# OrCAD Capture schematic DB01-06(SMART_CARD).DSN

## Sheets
1 01. Power Supply: size Custom; title: System Power; rev: 1.0; company: MEGAWIN; note: DB01-06
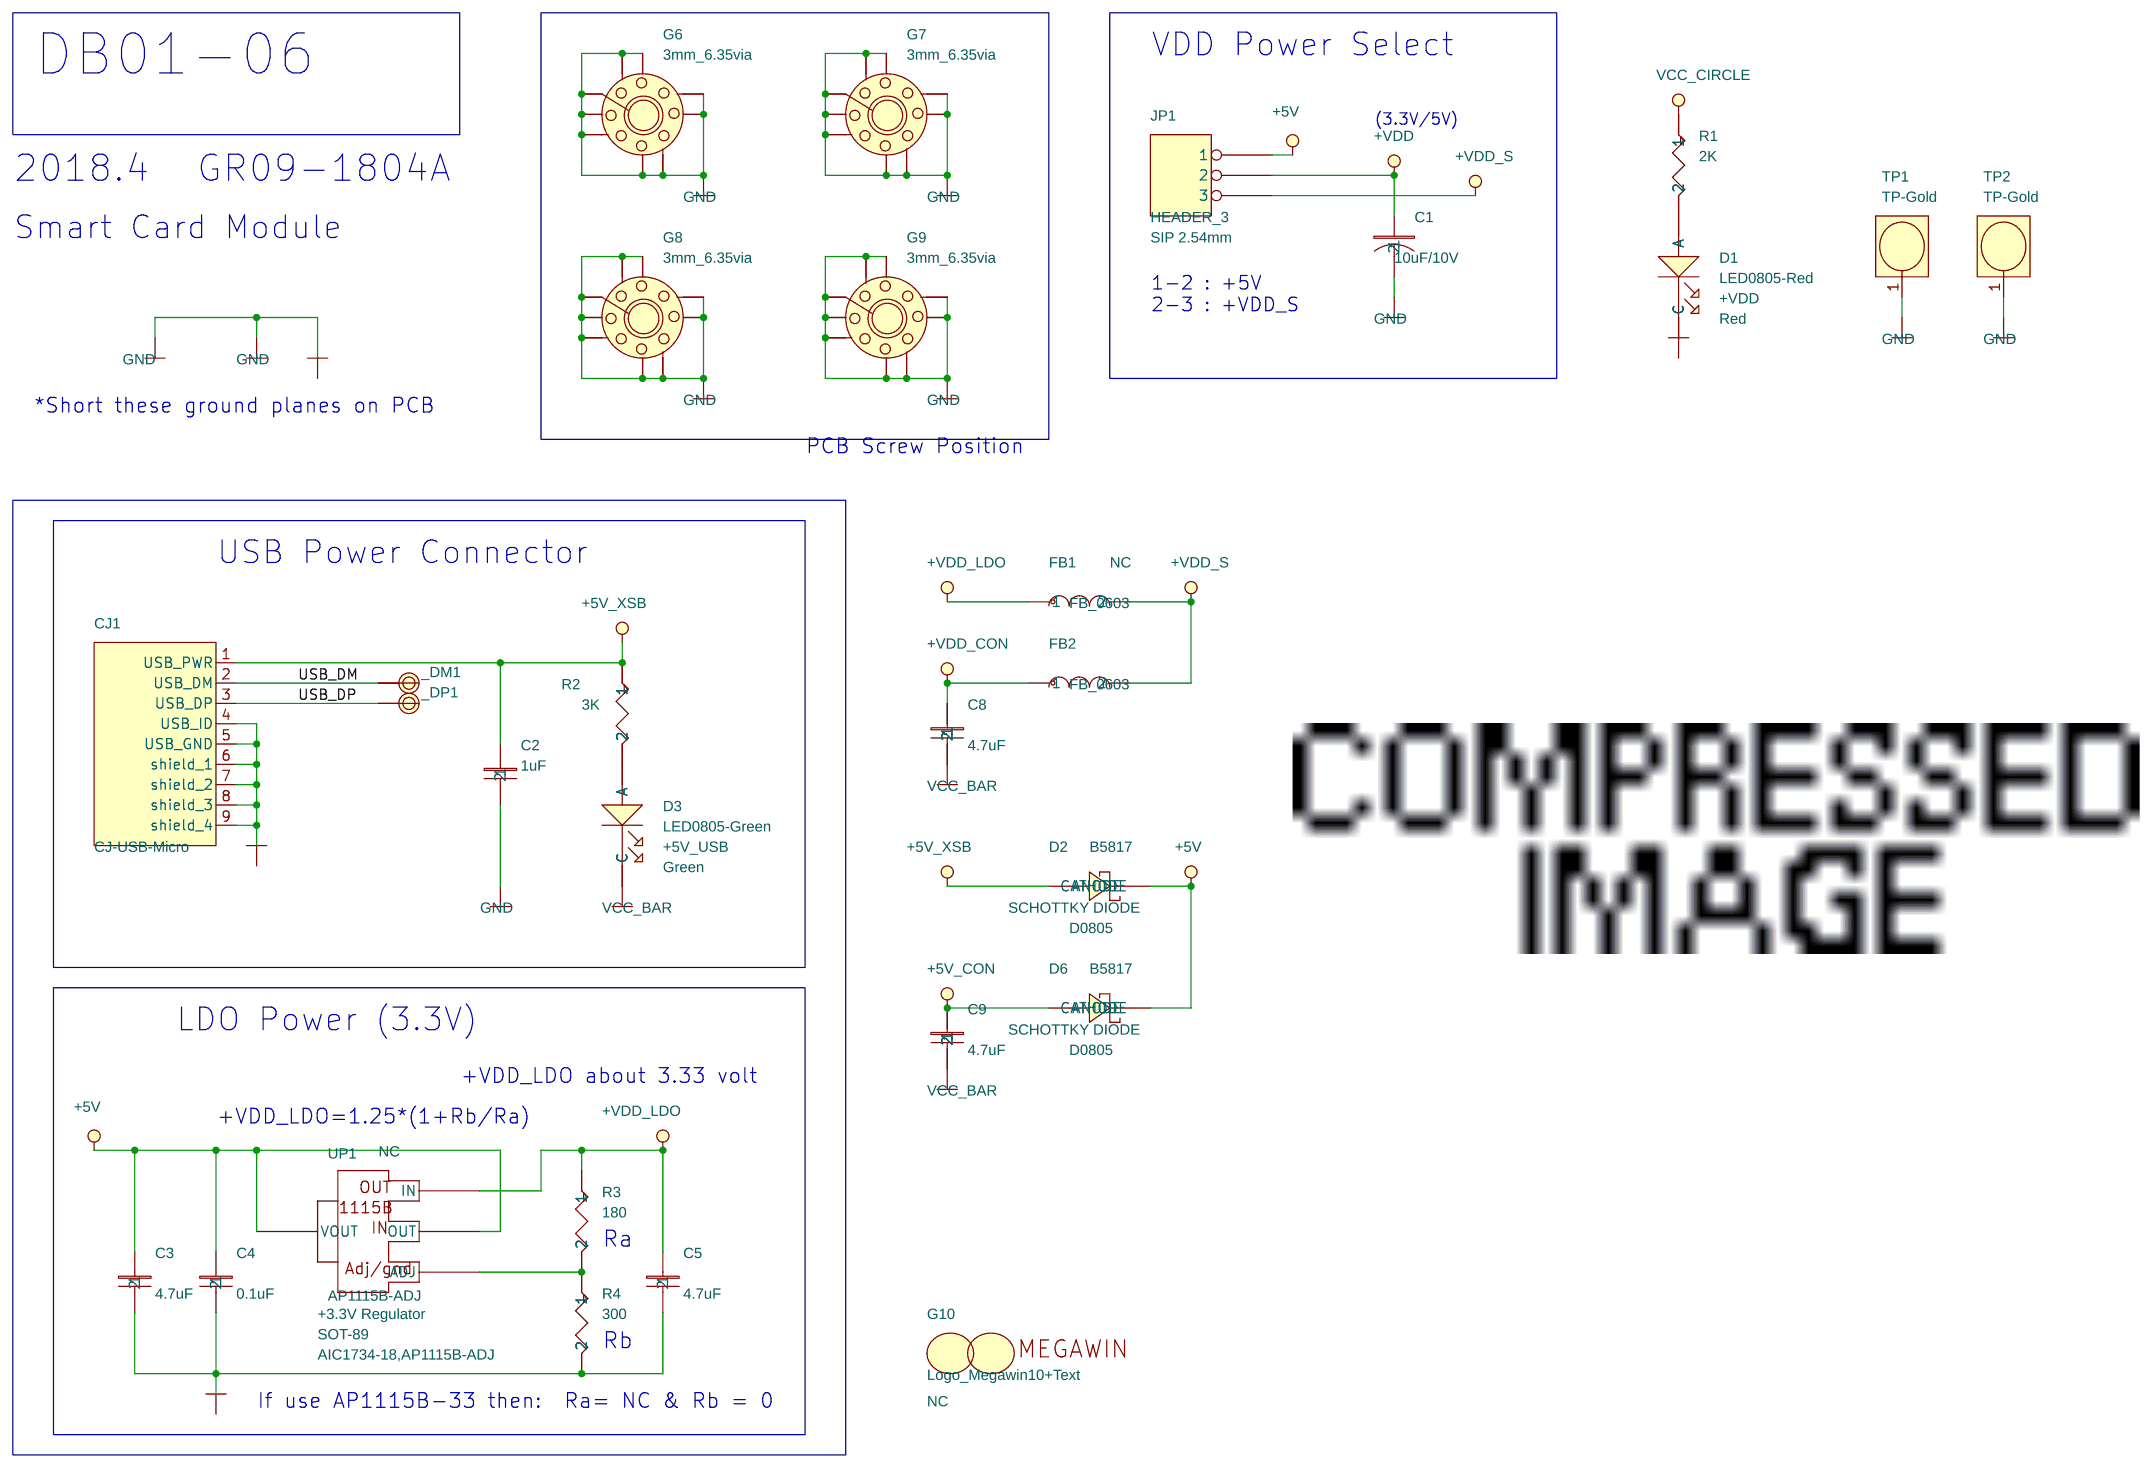
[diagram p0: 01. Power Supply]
2 02. Smart Card IF: size B; title: Smart Card Interface
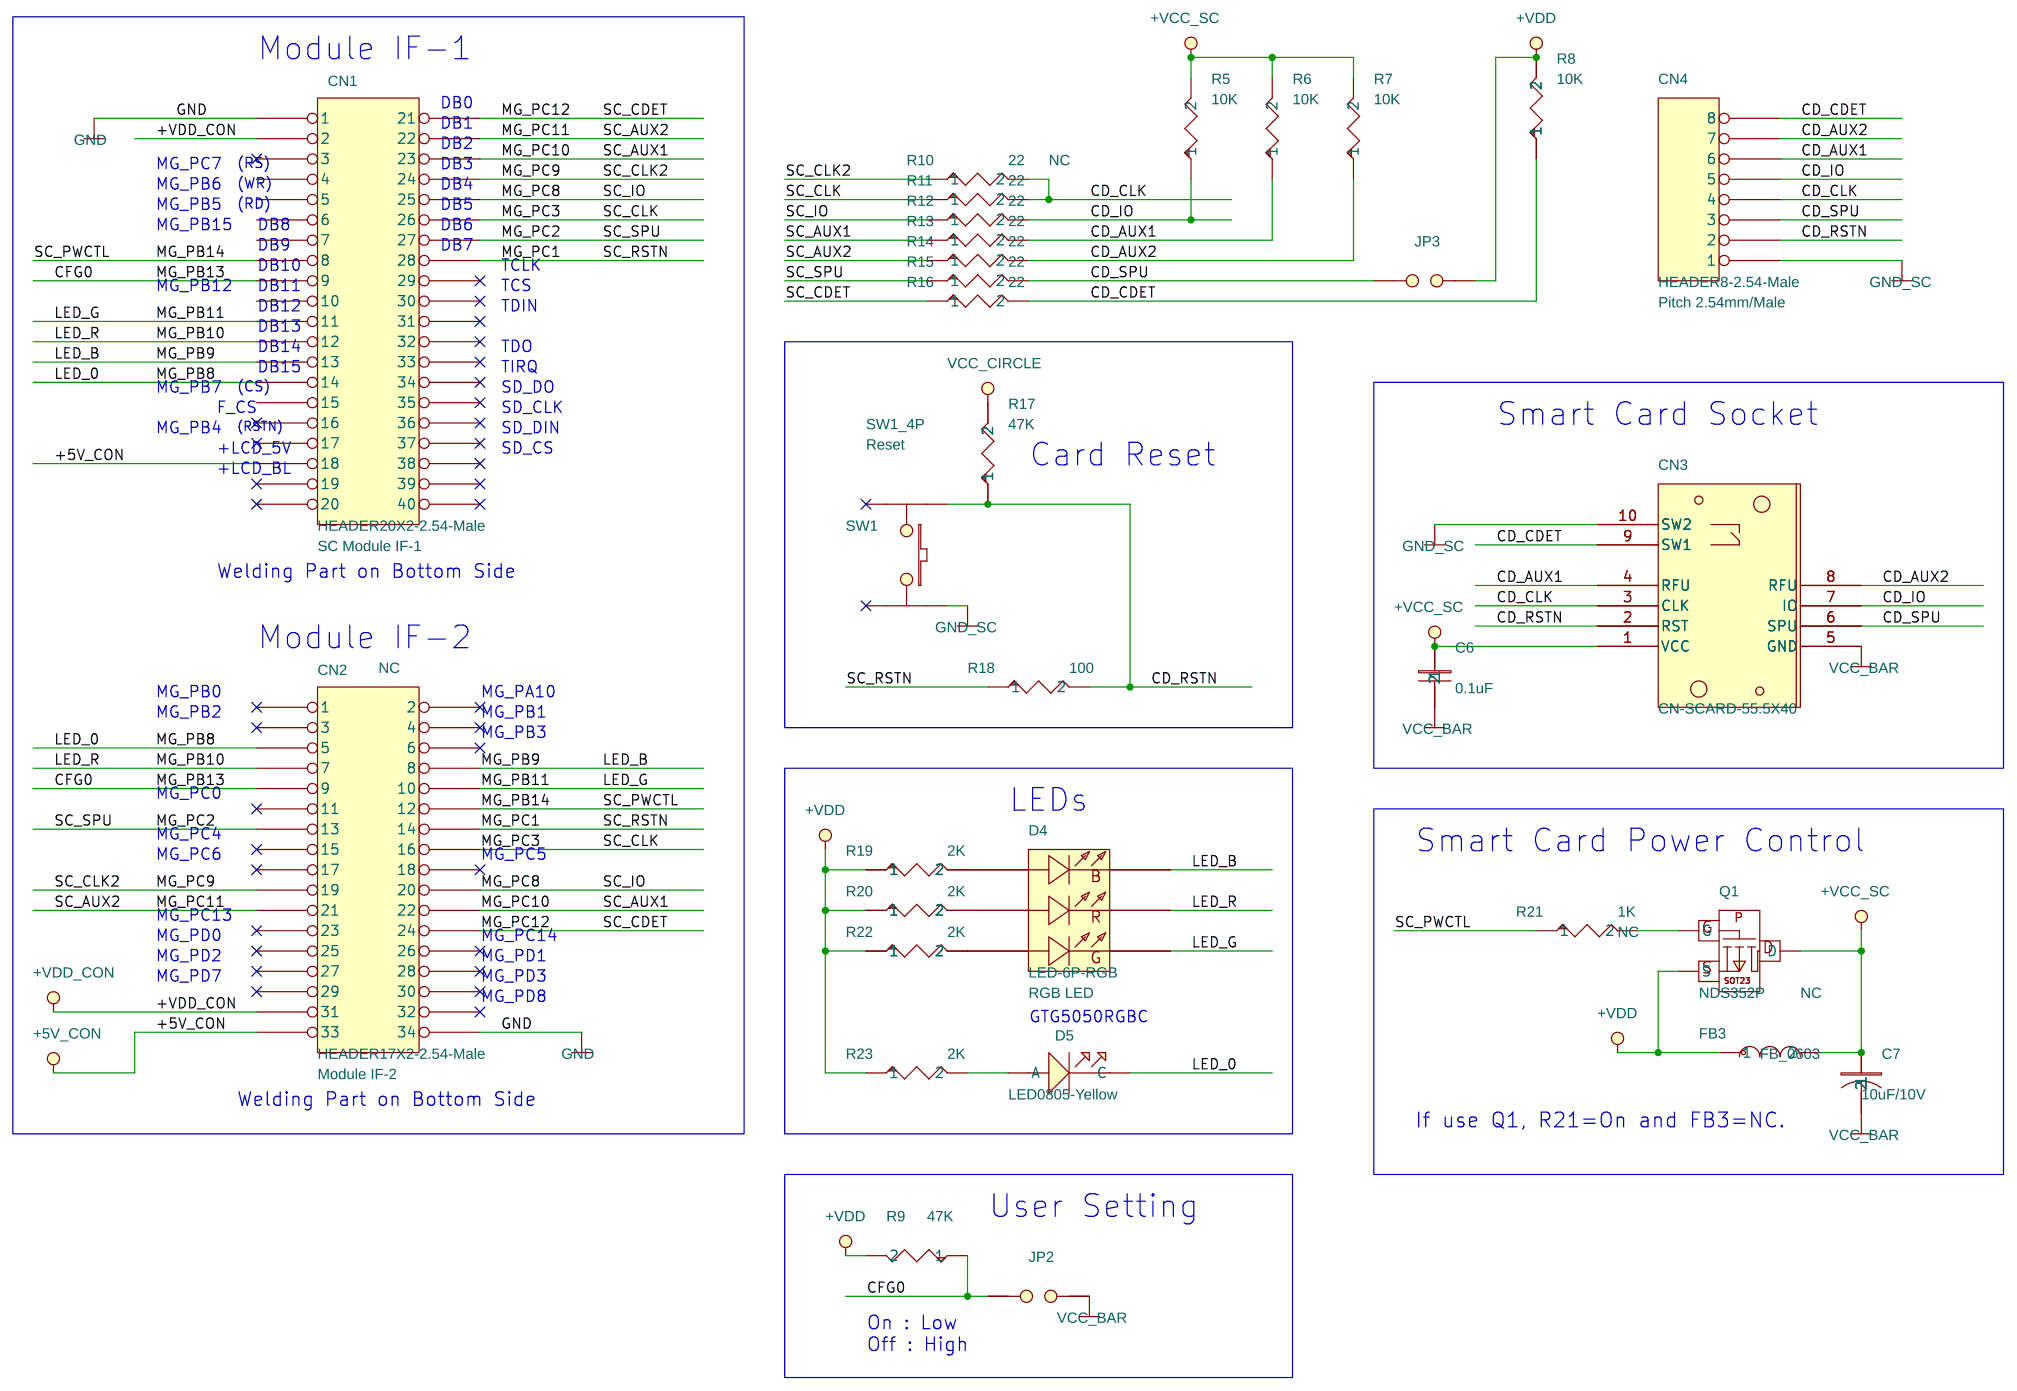
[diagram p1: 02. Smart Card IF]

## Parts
sheet 01. Power Supply
_DM1  TPH30  [TPH45]
_DP1  TPH30  [TPH45]
C1  10uF/10V  [C-0805]
C2  1uF  [C-0603]
C3  4.7uF  [C-0603]
C4  0.1uF  [C-0603]
C5  4.7uF  [C-0603]
C8  4.7uF  [C-0603]
C9  4.7uF  [C-0603]
CJ1  CJ-USB-Micro  [USB5-MICRO-290X220P065]
D1  LED0805-Red  [LED-0805]
D2  B5817  [D-0805]
D3  LED0805-Green  [LED-0805]
D6  B5817  [D-0805]
FB1  FB_0603  [L-0603]
FB2  FB_0603  [L-0603]
G6  3mm_6.35via  [SCREW9-H3-R6.35]
G7  3mm_6.35via  [SCREW9-H3-R6.35]
G8  3mm_6.35via  [SCREW9-H3-R6.35]
G9  3mm_6.35via  [SCREW9-H3-R6.35]
G10  Logo_Megawin10+Text  [MEGAWIN10_1]
JP1  HEADER_3  [SIP3-P2.54]
R1  2K  [R-0603]
R2  3K  [R-0603]
R3  180  [R-0603]
R4  300  [R-0603]
TP1  TP-Gold  [SIP1-39]
TP2  TP-Gold  [SIP1-39]
UP1  AP1115B-ADJ  [SOT-89-1]
sheet 02. Smart Card IF
C6  0.1uF  [C-0603]
C7  10uF/10V  [C-0805]
CN1  HEADER20X2-2.54-Male  [HD20X2A-P2.54]
CN2  HEADER17X2-2.54-Male  [HD17X2-P2.54]
CN3  CN-SCARD-55.5X40  [CARD-SMART-55.5X40]
CN4  HEADER8-2.54-Male  [SIP8-P2.54]
D4  LED-6P-RGB  [LED-6P-RGB-50X50]
D5  LED0805-Yellow  [LED-0805]
FB3  FB_0603  [L-0603]
JP2  JUMPER  [SIP2-P2.54-JUMPER]
JP3  JUMPER  [SIP2-P2.54-JUMPER]
Q1  NDS352P  [SOT-23]
R5  10K  [R-0603]
R6  10K  [R-0603]
R7  10K  [R-0603]
R8  10K  [R-0603]
R9  47K  [R-0603]
R10  22  [R-0603]
R11  22  [R-0603]
R12  22  [R-0603]
R13  22  [R-0603]
R14  22  [R-0603]
R15  22  [R-0603]
R16  22  [R-0603]
R17  47K  [R-0603]
R18  100  [R-0603]
R19  2K  [R-0603]
R20  2K  [R-0603]
R21  1K  [R-0603]
R22  2K  [R-0603]
R23  2K  [R-0603]
SW1  SW1_4P  [SW-TACT-P4.5X6.5-Z6.2X6.2X5]

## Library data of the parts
_DM1 _DP1 = TPH: Assembly: NC
C1 C7 = CAP-POL: Package: 1008 Multilayer Ceramic Chip Capacitor
C2 = CAP-NP_2: 2ND PART FIELD: SMD_0805; Package: 0603 Multilayer Ceramic Chip Capacitor
C3 = CAP-NP_1
C4 C6 = CAP-NP
C5 = CAP-NP_4
C8 = CAP-NP_5
C9 = CAP-NP_3
CJ1 = CJ-USB-Micro
D1 = LED: Assembly: Red; Function: +VDD; Package: Red
D2 D6 = DIODE-SCHOTTKY-2: Function: SCHOTTKY DIODE; Package: D0805
D3 = LED: Assembly: Green; Function: +5V_USB; Package: Red
FB1 = FB2_1: Assembly: NC
FB2 FB3 = FB2
G6-G9 = ScrewPad-9P: Assembly: NC; {PCB Footprint}: SCREW9-H3.5-R8
G10 = LOGO-Megawin10+Text: Assembly: NC
JP1 = HEADER3: 2ND PART FIELD: Pitch 2.54mm; Package: SIP 2.54mm
R1 = R: 2ND PART FIELD: SMD_0805; Package: 0603 SMD Resister
R2 R15 = R_2: 2ND PART FIELD: SMD_0805; Package: 0603 SMD Resister
R3 = R_3
R4 = R_1
TP1 TP2 = TPH-GND: Assembly: NC; Package: Gold Test Pin
UP1 = ICP-AP1115B: Alternate: AIC1734-18,AP1115B-ADJ; Assembly: NC; Function: +3.3V Regulator; Package: SOT-89
CN1 = HEADER20X2A: Function: SC Module IF-1
CN2 = HEADER17X2: Assembly: NC; Function: Module IF-2
CN3 = CN-SCARD-55.5X40
CN4 = HEADER8: Package: Pitch 2.54mm/Male
D4 = LED-6P-RGB: Function: RGB LED
D5 = LED: ATHEROS KEY: 127-00026-000; AtherosDescription: LED, THRU_HOLE,GREEN,3.0MM RADIAL; CISPartType: Diodes\LED
JP2 JP3 = JUMPER: Package: SIP2-RES
Q1 = MOS-P-SOT23: Assembly: NC
R5 = R_4: Package: 0603 SMD Resister
R6 = R_1: Package: 0603 SMD Resister
R7 = R_14: Package: 0603 SMD Resister
R8 = R_10: Package: 0603 SMD Resister
R9 = R_12: Package: 0603 SMD Resister
R10 = R_7: 2ND PART FIELD: SMD_0805; Assembly: NC; Package: 0603 SMD Resister
R11 = R_11: 2ND PART FIELD: SMD_0805; Package: 0603 SMD Resister
R12 = R_6: 2ND PART FIELD: SMD_0805; Package: 0603 SMD Resister
R13 = R_16: 2ND PART FIELD: SMD_0805; Package: 0603 SMD Resister
R14 = R_18: 2ND PART FIELD: SMD_0805; Package: 0603 SMD Resister
R16 = R_5: 2ND PART FIELD: SMD_0805; Package: 0603 SMD Resister
R17 = R_13: Package: 0603 SMD Resister
R18 = R_17: Package: 0603 SMD Resister
R19 = R_3: 2ND PART FIELD: SMD_0805; Package: 0603 SMD Resister
R20 = R_15: 2ND PART FIELD: SMD_0805; Package: 0603 SMD Resister
R21 = R: Assembly: NC; Package: 0603 SMD Resister
R22 = R_8: 2ND PART FIELD: SMD_0805; Package: 0603 SMD Resister
R23 = R_9: 2ND PART FIELD: SMD_0805; Package: 0603 SMD Resister
SW1 = SW-PB-4P: Function: Reset

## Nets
+5V: C3.1 C4.1 D2.2(CATHODE) D6.2(CATHODE) JP1.1 UP1.2(OUT) UP1.4(VOUT)
+5V_CON: C9.1 CN1.18 CN2.33 D6.1(ANODE)
+5V_XSB: C2.1 CJ1.1(USB_PWR) D2.1(ANODE) R2.1
+VCC_SC: C6.1 C7.1 CN3.1(VCC) FB3.2 Q1.3(D) R5.2 R6.2 R7.2 R17.2
+VDD: C1.1 FB3.1 JP1.2 JP3.2 Q1.2(S) R1.1 R8.2 R9.2 R19.1 R20.1 R22.1 R23.1
+VDD_CON: C8.1 CN1.2 CN2.31 FB2.1
+VDD_LDO: C5.1 FB1.1 R3.1 UP1.3(IN)
+VDD_S: FB1.2 FB2.2 JP1.3
GND: C1.2 C2.2 C3.2 C4.2 C5.2 C6.2 C7.2 C8.2 C9.2 CJ1.4(USB_ID) CJ1.5(USB_GND) CJ1.6(shield_1) CJ1.7(shield_2) CJ1.8(shield_3) CJ1.9(shield_4) CN1.1 CN2.34 CN3.5(GND) CN3.10(SW2) CN4.1 D1.2(C) D3.2(C) G6.1 G6.2 G6.3 G6.4 G6.5 G6.6 G6.7 G6.8 G6.9 G7.1 G7.2 G7.3 G7.4 G7.5 G7.6 G7.7 G7.8 G7.9 G8.1 G8.2 G8.3 G8.4 G8.5 G8.6 G8.7 G8.8 G8.9 G9.1 G9.2 G9.3 G9.4 G9.5 G9.6 G9.7 G9.8 G9.9 JP2.2 R4.2 SW1.2 TP1.1 TP2.1
CD_AUX1: CN3.4(RFU) CN4.6 R6.1 R13.2
CD_AUX2: CN3.8(RFU) CN4.7 R7.1 R14.2
CD_CDET: CN3.9(SW1) CN4.8 R8.1 R16.2
CD_CLK: CN3.3(CLK) CN4.4 R10.2 R11.2
CD_IO: CN3.7(IO) CN4.5 R5.1 R12.2
CD_RSTN: CN3.2(RST) CN4.2 R17.1 R18.2 SW1.1
CD_SPU: CN3.6(SPU) CN4.3 JP3.1 R15.2
CFG0: CN1.9 CN2.9 JP2.1 R9.1
LED_0: CN1.14 CN2.5 D5.2(C)
LED_B: CN1.13 CN2.8 D4.2
LED_G: CN1.11 CN2.10 D4.6
LED_R: CN1.12 CN2.7 D4.4
MG_PB14: CN1.8 CN2.12 R21.1
MG_PC1: CN1.28 CN2.14 R18.1
MG_PC2: CN1.27 CN2.13 R15.1
MG_PC3: CN1.26 CN2.16 R11.1
MG_PC8: CN1.25 CN2.20 R12.1
MG_PC9: CN1.24 CN2.19 R10.1
MG_PC10: CN1.23 CN2.22 R13.1
MG_PC11: CN1.22 CN2.21 R14.1
MG_PC12: CN1.21 CN2.24 R16.1
USB_DM: _DM1.1 CJ1.2(USB_DM)
USB_DP: _DP1.1 CJ1.3(USB_DP)
N66229482: R3.2 R4.1 UP1.1(ADJ)
N66338352: Q1.1(G) R21.2
N66382641: D5.1(A) R23.2
N66393948: D4.3 R20.2
N66393949: D4.5 R22.2
N66393950: D4.1 R19.2
N66396998: D3.1(A) R2.2
N66397195: D1.1(A) R1.2

Not connected (* = marked no-connect by the designer): CN1 3* 4 5 6 7 10 15 16* 17* 19* 20* 29* 30* 31* 32* 33* 34* 35* 36* 37* 38* 39* 40*; CN2 1* 2* 3* 4* 6* 11* 15* 17* 18* 23* 25* 26* 27* 28* 29* 30* 32*; G10 1(.); SW1 3* 4*

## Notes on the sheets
sheet 1
- DB01-06
- VDD Power Select
- (3.3V/5V)
- 2018.4
- GR09-1804A
- Smart Card Module
- 1-2 : +5V
  2-3 : +VDD_S
- *Short these ground planes on PCB
- PCB Screw Position
- USB Power Connector
- LDO Power (3.3V)
- +VDD_LDO about 3.33 volt
- +VDD_LDO=1.25*(1+Rb/Ra)
- Ra
- Rb
- If use AP1115B-33 then:  Ra= NC & Rb = 0
sheet 2
- Module IF-1
- DB0
- DB1
- DB2
- MG_PC7
- (RS)
- DB3
- MG_PB6
- (WR)
- DB4
- MG_PB5
- (RD)
- DB5
- MG_PB15
- DB8
- DB9
- DB6
- DB7
- DB10
- TCLK
- MG_PB12
- DB11
- TCS
- DB12
- TDIN
- DB13
- DB14
- DB15
- TDO
- TIRQ
- MG_PB7
- (CS)
- SD_DO
- F_CS
- SD_CLK
- Smart Card Socket
- MG_PB4
- (RSTN)
- SD_DIN
- +LCD_5V
- SD_CS
- Card Reset
- +LCD_BL
- Welding Part on Bottom Side
- Module IF-2
- MG_PB0
- MG_PA10
- MG_PB2
- MG_PB1
- MG_PB3
- MG_PC0
- LEDs
- MG_PC4
- Smart Card Power Control
- MG_PC6
- MG_PC5
- MG_PC13
- MG_PD0
- MG_PC14
- MG_PD2
- MG_PD1
- MG_PD7
- MG_PD3
- MG_PD8
- GTG5050RGBC
- Welding Part on Bottom Side
- If use Q1, R21=On and FB3=NC.
- User Setting
- On : Low
  Off : High
